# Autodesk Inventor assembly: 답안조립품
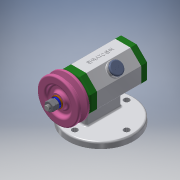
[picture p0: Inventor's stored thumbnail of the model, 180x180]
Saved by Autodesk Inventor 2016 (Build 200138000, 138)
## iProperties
Created: 2021-02
Part Number: 답안조립품
Material: 일반
Document SubType Name: Assembly
Designer: CAD2
Author: CAD2
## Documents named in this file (14)
- C:\Users\CAD2\Desktop\710204V1003\답안조립품.iam
- C:\Users\CAD2\Desktop\710204V1003\본체.ipt
- C:\Users\CAD2\Desktop\710204V1003\V벨트풀리.ipt
- C:\Users\CAD2\Desktop\710204V1003\고무캡.ipt
- C:\Users\CAD2\Desktop\710204V1003\너트 M8.ipt
- C:\Users\CAD2\Desktop\710204V1003\뒤커버.ipt
- C:\Users\CAD2\Desktop\710204V1003\베어링 15 x 32 x 9.ipt
- C:\Users\CAD2\Desktop\710204V1003\볼트 M4 x 12.ipt
- C:\Users\CAD2\Desktop\710204V1003\스프링와셔 8.ipt
- C:\Users\CAD2\Desktop\710204V1003\앞커버.ipt
- C:\Users\CAD2\Desktop\710204V1003\오일 실 15 25 7.ipt
- C:\Users\CAD2\Desktop\710204V1003\와셔 8x17.ipt
- C:\Users\CAD2\Desktop\710204V1003\축.ipt
- C:\Users\CAD2\Desktop\710204V1003\키 3 x 3 x 12.ipt
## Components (2 placed, 2 different names)
1. V벨트풀리:1 — 각도:2
2. 고무캡:1
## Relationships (1: Angle 1)
- 각도:2 [Angle]: V벨트풀리:1
